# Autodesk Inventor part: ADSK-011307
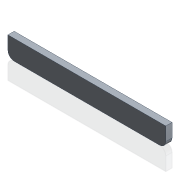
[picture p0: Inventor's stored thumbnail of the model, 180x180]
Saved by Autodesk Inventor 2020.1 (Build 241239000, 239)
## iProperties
Created: 1999-12
Part Number: ADSK-011307
Material: Pearson Aluminium
Document SubType Name: Modeling
Designer: sspink
Density: 2.71 g/cm^3
Appearance: Pearson-Aluminum
Mass: 46.7076 g
Surface Area: 77.6619 cm^2
Volume: 17.2353 cm^3
Control State: 0
Checked Out: False
Master: False
Shininess: 35.0
Length Units: 11269
Angle Units: 11279
Time Units: 11290
Mass Units: 11283
Length Display Precision: 3
Angle Display Precision: 2
Compacted: True
Cutlength: 6
Material Desc: FLAT,ALUM,0.25 X 0.75
Material_number: A087929
Dimensions: 152x19x6 mm
Mass: 0,047 kg
DocNumber: ADSK-011307.ipt
Folder: 01 - Themengebiete\Simplification\01 - Packaging machine\
VDS_Category: 3D Komponenten
Density: 2.71
Volumn: 18.325575131353986
Area: 79.14628739548746
PropertySet Name: Model Information
Author: sspink
Revision Number: -
Title: support
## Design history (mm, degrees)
node "Solide1"
  node "Extrusion1" dims "d2" = 6, "d3" = 0
  node "Fillet1" dims "d4" = 6
sketch "Sketch1"
  geometry: L1 (-53.551, -0.242)-(-205.551, -0.242) reference; L2 (-205.551, -0.242)-(-205.551, 18.758) reference; L3 (-205.551, 18.758)-(-53.551, 18.758); L4 (-53.551, 18.758)-(-53.551, -0.242)
  constraints: 8 end point, 2 horizontal, 2 parallel, 1 perpendicular, 1 vertical
  dimensions: "d0" = 19 distance of L3.end L1.start; "d1" = 152 distance of L1.start L1.end
node "Corps solides"
node "Corps surfaciques"
